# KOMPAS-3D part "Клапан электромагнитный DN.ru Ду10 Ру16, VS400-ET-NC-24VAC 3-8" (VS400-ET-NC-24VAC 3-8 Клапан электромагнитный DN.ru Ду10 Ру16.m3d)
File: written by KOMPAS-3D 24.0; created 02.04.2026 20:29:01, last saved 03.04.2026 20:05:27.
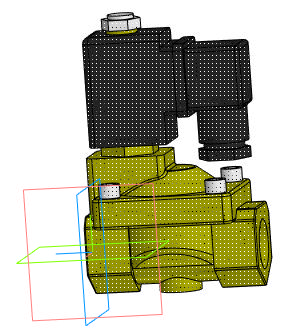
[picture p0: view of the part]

Document properties: Автор: artio; Полное имя файла: C:\Users\artio\OneDrive\Рабочий стол\Клапан электромагнитный DN.ru\VS400-ET-NC\VS400-ET-NC-24VAC 3-8 Клапан электромагнитный DN.ru Ду10 Ру16.m3d

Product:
- Body: Тело 1  | qty 1
    Масса: 1.030062
- Part/product: Клапан электромагнитный DN.ru Ду10 Ру16  | designation VS400-ET-NC-24VAC 3-8
    Масса: 0.797
    Раздел спецификации: Прочие изделия
    Примечание: D130-05628
    additional columns: ef56311e-7521-43dc-8291-0e6108b3d81d; VS400-ET-NC-220VAC 3-8; artio; c; Шероховатость не задана; Да

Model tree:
1. Операция без истории:1

Expressions: VS400-ET-NC-24VAC 3-8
